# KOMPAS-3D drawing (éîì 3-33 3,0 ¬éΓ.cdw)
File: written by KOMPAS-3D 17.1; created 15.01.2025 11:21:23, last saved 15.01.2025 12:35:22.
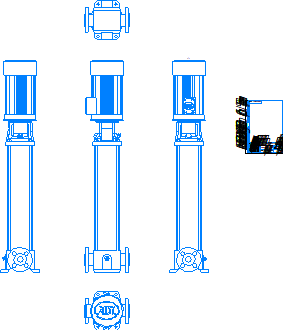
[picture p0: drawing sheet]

Sheet 1: A4, portrait

Title block, sheet 1: name: ВМН 3-33 3,0 кВт; designation: ВМН 3-33 3,0 кВт; material: Сталь 10  ГОСТ 1050-2013; mass: 68,16; sheets: 1; sheet format: A4; stored path: \\adlc.lan\data\АДЛ_ПКД\3D-модели\ADL production\Насосы ГРАНПАМП\Насосы ВМН\ВМН3\KOMPAS 3D\ВМН 3-33 3,0 кВт.cdw

Views: Проекционный вид 2, Проекционный вид 3, Проекционный вид 4, Проекционный вид 5
Referenced files in \\adlc.lan\data\АДЛ_ПКД\3D-модели\ADL production\Насосы ГРАНПАМП\Насосы ВМН\ВМН3\KOMPAS 3D\: ВМН 3-33 3,0 кВт.m3d
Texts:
  Andrey
  АДЛ
Dimensions and other numbers on the sheet: 1:1; 1; 68,16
